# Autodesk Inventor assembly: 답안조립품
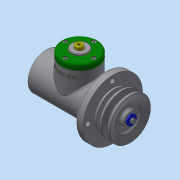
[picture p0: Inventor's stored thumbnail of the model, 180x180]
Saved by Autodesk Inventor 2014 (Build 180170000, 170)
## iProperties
Created: 2016-08
Part Number: 답안조립품
Document SubType Name: Assembly
Designer: 703-04
Author: 703-04
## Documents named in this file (25)
- C:\Users\703-04\Desktop\460808V1021\답안조립품.iam
- C:\Users\703-04\Desktop\460808V1021\본체.ipt
- C:\Users\703-04\Desktop\460808V1021\V-벨트풀리.ipt
- C:\Users\703-04\Desktop\460808V1021\너트 M10.ipt
- C:\Users\703-04\Desktop\460808V1021\링크.ipt
- C:\Users\703-04\Desktop\460808V1021\멈춤링 15 x 1.ipt
- C:\Users\703-04\Desktop\460808V1021\멈춤링 35x1.6.ipt
- C:\Users\703-04\Desktop\460808V1021\베어링 15 x 35 x 11.ipt
- C:\Users\703-04\Desktop\460808V1021\볼트 M4 x 10.ipt
- C:\Users\703-04\Desktop\460808V1021\볼트 M4 x 12.ipt
- C:\Users\703-04\Desktop\460808V1021\부시1.ipt
- C:\Users\703-04\Desktop\460808V1021\부시2.ipt
- C:\Users\703-04\Desktop\460808V1021\분할핀 1.6 x 12.ipt
- C:\Users\703-04\Desktop\460808V1021\사이드 커버.ipt
- 사이드 커버.ipt
- C:\Users\703-04\Desktop\460808V1021\슬라이더.ipt
- C:\Users\703-04\Desktop\460808V1021\오일 실 15 25 7.ipt
- C:\Users\703-04\Desktop\460808V1021\와셔 4x16.ipt
- C:\Users\703-04\Desktop\460808V1021\와셔 10x21.ipt
- C:\Users\703-04\Desktop\460808V1021\클래스터 핀 6 x 24.ipt
- C:\Users\703-04\Desktop\460808V1021\키 4 x 4 x 18.ipt
- C:\Users\703-04\Desktop\460808V1021\탑 부시.ipt
- C:\Users\703-04\Desktop\460808V1021\탑 커버.ipt
- 탑 커버.ipt
- C:\Users\703-04\Desktop\460808V1021\편심축.ipt
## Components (6 placed, 3 different names)
1. V-벨트풀리:1
2. ISO 4017 M4 x 10:1
3. ISO 4762 M4 x 12:1
4. ISO 4762 M4 x 12:2
5. ISO 4762 M4 x 12:3
6. ISO 4762 M4 x 12:4
